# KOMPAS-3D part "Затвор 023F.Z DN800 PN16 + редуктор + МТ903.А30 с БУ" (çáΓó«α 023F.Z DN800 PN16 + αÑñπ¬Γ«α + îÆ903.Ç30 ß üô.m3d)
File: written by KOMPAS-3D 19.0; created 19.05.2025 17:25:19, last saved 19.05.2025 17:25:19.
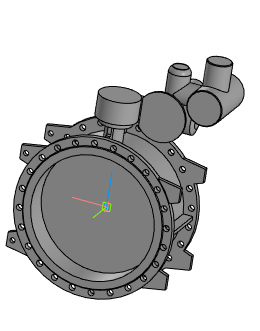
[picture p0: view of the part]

Document properties: Полное имя файла: Затвор 023F.Z DN800 PN16 + редуктор + МТ903.А30 с БУ.a3d

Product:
- Part/product: Затвор 023F.Z DN800 PN16 + редуктор + МТ903.А30 с БУ
    Масса: 1084.79

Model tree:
1. Операция без истории:1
